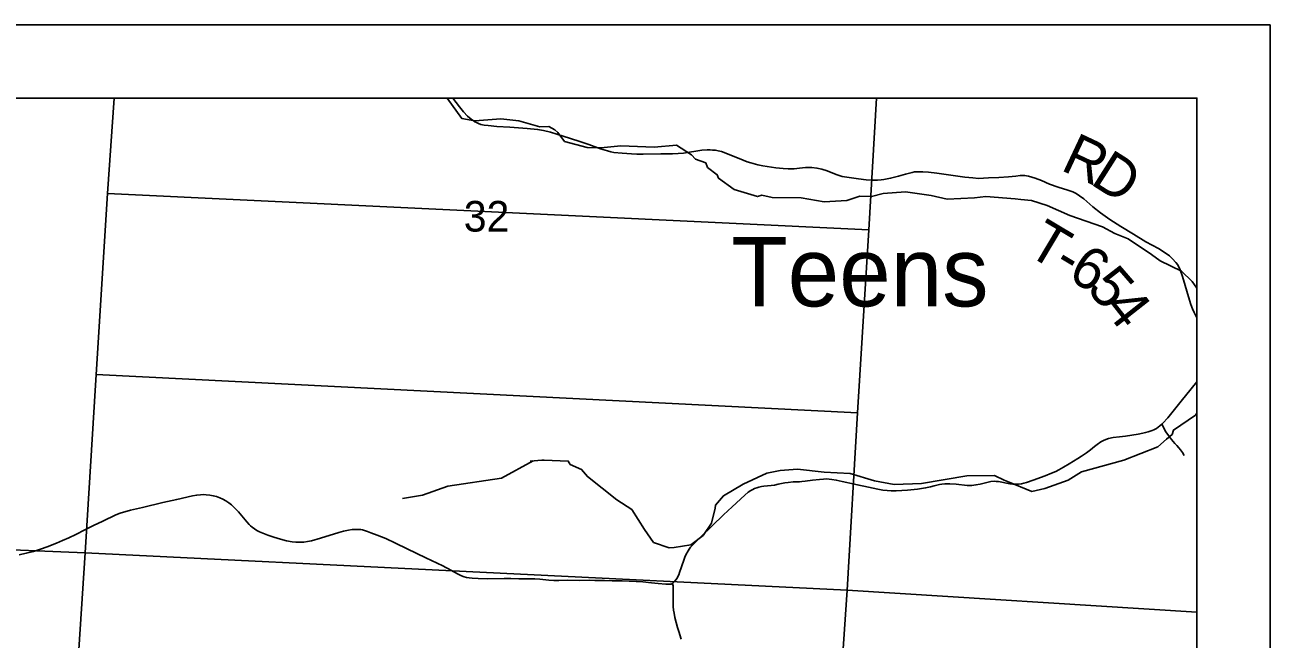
# Model space of a CAD drawing. Extents: x 0 to 34, y 0 to 22.
# Drawn here: x 7.297 to 9, y 20.161 to 21 of the extents above; entities that cross this region are included whole.
import ezdxf

# ---------------------------------------------------------------- set-up
doc = ezdxf.new("R2010")
doc.units = 0
for name, color, linetype in [('Default', 7, 'Continuous'), ('GM_X_County_Road', 7, 'Continuous'), ('GM_X_Minor_River', 7, 'Continuous'), ('GM_X_Minor_River_Text', 7, 'Continuous'), ('GM_X_Section', 7, 'Continuous'), ('GM_X_Section_Text', 7, 'Continuous'), ('GM_X_Township_Road', 7, 'Continuous'), ('GM_X_Township_Road_Text', 7, 'Continuous'), ('SH_Cut_Line', 7, 'Continuous'), ('SH_Data', 7, 'Continuous')]:
    doc.layers.add(name, color=color, linetype=linetype)

msp = doc.modelspace()

# ---------------------------------------------------------------- linework, layer by layer
at = {"layer": 'Default'}
for points in [[(7.4193, 20.9), (6.3675, 20.9), (6.3282, 20.3221), (7.3795, 20.2788), (7.3949, 20.5225), (7.4104, 20.7697)], [(8.4618, 20.9), (7.4193, 20.9), (7.4104, 20.7697), (8.4511, 20.7202)], [(8.9, 20.1978), (8.9, 20.9), (8.4618, 20.9), (8.4511, 20.7202), (8.4356, 20.4701), (8.4216, 20.2279)], [(8.9, 19.9376), (8.9, 20.1978), (8.4216, 20.2279), (8.4033, 19.9608)]]:
    msp.add_lwpolyline(points, close=True, dxfattribs=at)
msp.add_lwpolyline([(7.1944, 19.2649), (8.4872, 19.2008), (8.8731, 19.181), (8.9, 19.1797), (8.9, 20.9), (6.3694, 20.9)], dxfattribs=at)
at = {"layer": 'GM_X_County_Road'}
for points in [[(7.2893, 20.2761), (7.299, 20.2783), (7.3088, 20.2808), (7.3184, 20.2837), (7.3277, 20.287), (7.3404, 20.2921), (7.3486, 20.2955), (7.3575, 20.2995), (7.3668, 20.304), (7.379, 20.3103), (7.391, 20.3163), (7.4037, 20.3223), (7.4217, 20.3305), (7.4273, 20.3328), (7.4323, 20.3345), (7.437, 20.3359), (7.4416, 20.3371), (7.458, 20.3408), (7.4859, 20.3475), (7.5048, 20.3519), (7.5265, 20.3566), (7.5322, 20.3576), (7.5375, 20.3582), (7.5413, 20.3583), (7.5452, 20.3582), (7.55, 20.3576), (7.5547, 20.3569), (7.5593, 20.3557), (7.5637, 20.3541), (7.5678, 20.3522), (7.572, 20.3498), (7.576, 20.3471), (7.5798, 20.3442), (7.5831, 20.3414), (7.5859, 20.3385), (7.5893, 20.3348), (7.5961, 20.3265), (7.6005, 20.3213), (7.6039, 20.3176), (7.6057, 20.3158), (7.6078, 20.314), (7.6112, 20.3114), (7.6146, 20.3094), (7.6181, 20.3075), (7.6225, 20.3056), (7.6296, 20.3029), (7.6377, 20.3001), (7.6466, 20.2975), (7.655, 20.2954), (7.6629, 20.294), (7.6678, 20.2934), (7.6711, 20.2932), (7.6745, 20.2932), (7.6788, 20.2935), (7.6836, 20.2942), (7.689, 20.2954), (7.7015, 20.299), (7.7264, 20.3065), (7.733, 20.3083), (7.7399, 20.3098), (7.7449, 20.3105), (7.7498, 20.3108), (7.7523, 20.3108), (7.7545, 20.3108), (7.7568, 20.3105), (7.759, 20.3101), (7.7617, 20.3094), (7.7657, 20.3081), (7.7704, 20.3063), (7.779, 20.3031), (7.7907, 20.2982), (7.8041, 20.292), (7.8198, 20.2845), (7.8454, 20.2722), (7.8688, 20.2609), (7.8728, 20.2589), (7.8766, 20.257), (7.8798, 20.2552), (7.8886, 20.2501), (7.8915, 20.2486), (7.8945, 20.2473), (7.8978, 20.2461), (7.9011, 20.2452), (7.9048, 20.2445), (7.9088, 20.2441), (7.9172, 20.2437), (7.9298, 20.2433), (7.9524, 20.2439), (7.9619, 20.2439), (7.9729, 20.2433), (7.9883, 20.2433), (7.9945, 20.2432), (8.0012, 20.2428), (8.0139, 20.2413), (8.0206, 20.2409), (8.0274, 20.2411), (8.0398, 20.2414), (8.0562, 20.2412), (8.0692, 20.2413), (8.0767, 20.2412), (8.09, 20.2408), (8.1002, 20.2407), (8.1138, 20.2406), (8.1234, 20.2403), (8.1331, 20.2398), (8.1424, 20.2391), (8.1541, 20.238), (8.1634, 20.2368), (8.1737, 20.2358), (8.1778, 20.2358), (8.181, 20.2361), (8.1828, 20.237), (8.1852, 20.2393), (8.1874, 20.2418), (8.189, 20.2441), (8.1903, 20.2463), (8.1913, 20.2488), (8.1926, 20.2521), (8.1983, 20.2687), (8.1998, 20.2729), (8.2012, 20.2759), (8.2041, 20.2815), (8.2057, 20.284), (8.2076, 20.2865), (8.212, 20.2913), (8.2215, 20.3007), (8.2527, 20.3306), (8.2644, 20.3416), (8.2815, 20.3575), (8.2863, 20.3615), (8.29, 20.3639), (8.2927, 20.3654), (8.2951, 20.3665), (8.298, 20.3676), (8.3008, 20.3685), (8.3044, 20.3693), (8.3075, 20.3697), (8.3176, 20.3707), (8.3223, 20.3713), (8.3274, 20.3724), (8.3365, 20.3743), (8.3412, 20.375), (8.3477, 20.3756), (8.3563, 20.3759), (8.3598, 20.3762), (8.3642, 20.3766), (8.3742, 20.3779), (8.3836, 20.3791), (8.3891, 20.3796), (8.394, 20.3797), (8.3972, 20.3796), (8.4006, 20.3792), (8.4068, 20.3782), (8.4146, 20.3763), (8.4318, 20.3725), (8.4377, 20.3713), (8.4444, 20.3699), (8.4509, 20.3684), (8.4636, 20.3658), (8.4704, 20.3645), (8.4762, 20.3638), (8.4817, 20.3634), (8.4885, 20.3634), (8.504, 20.3645), (8.5179, 20.3658), (8.5288, 20.3676), (8.5354, 20.3691), (8.5406, 20.3705), (8.548, 20.3722), (8.5512, 20.3726), (8.5552, 20.373), (8.5583, 20.373), (8.5621, 20.3729), (8.5706, 20.3724), (8.5856, 20.371), (8.5892, 20.3709), (8.5921, 20.371), (8.5977, 20.3715), (8.6035, 20.3728), (8.6127, 20.3751), (8.6179, 20.3762), (8.6226, 20.3765), (8.6256, 20.3764), (8.6287, 20.3761), (8.6443, 20.3732), (8.648, 20.3727), (8.6518, 20.3725), (8.656, 20.3728), (8.66, 20.3732), (8.6633, 20.3738), (8.667, 20.3748), (8.676, 20.3779), (8.6923, 20.384), (8.7013, 20.3877), (8.7069, 20.39), (8.7111, 20.3922), (8.7176, 20.3959), (8.7251, 20.4003), (8.7371, 20.4075), (8.7423, 20.4107), (8.7488, 20.4153), (8.7543, 20.4195), (8.7598, 20.424), (8.7636, 20.427), (8.7687, 20.4304), (8.7731, 20.4328), (8.7789, 20.435), (8.7854, 20.4363), (8.7939, 20.4374), (8.8021, 20.4384), (8.8197, 20.4411), (8.8258, 20.4423), (8.8297, 20.4431), (8.8331, 20.444), (8.836, 20.4449), (8.8388, 20.446), (8.8412, 20.447), (8.8445, 20.4487), (8.847, 20.4504), (8.8492, 20.4521), (8.8521, 20.4546), (8.8532, 20.4558), (8.86, 20.4633), (8.8782, 20.4859), (8.8922, 20.5029), (8.9, 20.5124)], [(8.1948, 20.1609), (8.1913, 20.1715), (8.1896, 20.1768), (8.1877, 20.1838), (8.1861, 20.1903), (8.1849, 20.1964), (8.1843, 20.2005), (8.1839, 20.2053), (8.1837, 20.2099), (8.1836, 20.2148), (8.1837, 20.2255), (8.1838, 20.2337), (8.1828, 20.237)]]:
    msp.add_lwpolyline(points, dxfattribs=at)
at = {"layer": 'GM_X_Minor_River'}
for points in [[(8.9, 20.6406), (8.8933, 20.6494), (8.8789, 20.6635), (8.8498, 20.6775), (8.838, 20.6862), (8.8059, 20.7078), (8.7877, 20.715), (8.7707, 20.724), (8.7261, 20.7395), (8.6951, 20.7535), (8.6739, 20.7603), (8.6592, 20.7614), (8.6516, 20.7622), (8.6115, 20.7655), (8.596, 20.7636), (8.5586, 20.7619), (8.5363, 20.7668), (8.5015, 20.7721), (8.4709, 20.7697), (8.455, 20.7655), (8.4391, 20.7659), (8.421, 20.7601), (8.3904, 20.7581), (8.3586, 20.7638), (8.3189, 20.7644), (8.3049, 20.7674), (8.2989, 20.7655), (8.2671, 20.7753), (8.2459, 20.7905), (8.244, 20.7954), (8.2308, 20.8053), (8.2282, 20.8114), (8.2142, 20.8167), (8.2089, 20.8227), (8.1884, 20.8356), (8.1578, 20.8329), (8.1121, 20.8347), (8.0849, 20.8319), (8.066, 20.8327), (8.0353, 20.8406), (8.0259, 20.8531), (8.0217, 20.8569), (8.0138, 20.8614), (8.0013, 20.861), (7.9725, 20.8689), (7.948, 20.8719), (7.9124, 20.8692), (7.8947, 20.8722), (7.8749, 20.9)], [(8.9, 20.4696), (8.898, 20.467), (8.8678, 20.4464), (8.8659, 20.4407), (8.8583, 20.4342), (8.8466, 20.4235), (8.8002, 20.4052), (8.7423, 20.3895), (8.7238, 20.378), (8.6921, 20.3665), (8.6743, 20.3627), (8.641, 20.3763), (8.6365, 20.3782), (8.6233, 20.3846), (8.5851, 20.3838), (8.5235, 20.3737), (8.4861, 20.3721), (8.4592, 20.377), (8.4259, 20.3872), (8.3904, 20.389), (8.3537, 20.3931), (8.3299, 20.3911), (8.3118, 20.3877), (8.2793, 20.3728), (8.2525, 20.3568), (8.2415, 20.3438), (8.2411, 20.34), (8.2362, 20.3195), (8.2249, 20.3027), (8.2079, 20.2897), (8.1849, 20.2863), (8.1781, 20.2855), (8.1569, 20.293), (8.1444, 20.3109), (8.127, 20.3378), (8.1065, 20.3511), (8.0664, 20.3829), (8.0585, 20.3928), (8.043, 20.3996), (8.0403, 20.4042), (8.0074, 20.4056), (8.004, 20.4056), (7.9882, 20.404)], [(7.9922, 20.4044), (7.9492, 20.3806), (7.8755, 20.3697), (7.8408, 20.3575), (7.8138, 20.3531)]]:
    msp.add_lwpolyline(points, dxfattribs=at)
at = {"layer": 'GM_X_Section'}
for points in [[(7.4104, 20.7697), (8.4511, 20.7202), (8.4356, 20.4701), (7.3949, 20.5225)], [(8.4356, 20.4701), (8.4216, 20.2279), (7.3795, 20.2788), (7.3949, 20.5225)], [(6.3282, 20.3221), (7.3795, 20.2788), (7.3627, 20.0215), (7.3466, 19.7773), (7.3307, 19.5247), (7.3152, 19.2658), (6.2595, 19.3129)], [(8.4216, 20.2279), (8.4033, 19.9608), (7.3627, 20.0215), (7.3795, 20.2788)]]:
    msp.add_lwpolyline(points, close=True, dxfattribs=at)
at = {"layer": 'GM_X_Township_Road'}
for points in [[(7.8825, 20.9), (7.8915, 20.8883), (7.897, 20.8814), (7.9027, 20.8755), (7.9077, 20.8712), (7.9101, 20.8694), (7.9126, 20.8678), (7.9149, 20.8666), (7.9174, 20.8653), (7.9209, 20.8641), (7.9251, 20.8631), (7.9309, 20.8624), (7.9428, 20.8614), (7.9605, 20.8603), (7.9841, 20.8587), (7.9984, 20.8573), (8.0063, 20.8559), (8.016, 20.8536), (8.0334, 20.8479), (8.0545, 20.841), (8.0682, 20.8366), (8.0844, 20.8309), (8.0939, 20.8278), (8.0987, 20.8265), (8.1028, 20.8259), (8.1139, 20.8247), (8.1266, 20.8237), (8.134, 20.8234), (8.1429, 20.8234), (8.1668, 20.8237), (8.1827, 20.824), (8.1907, 20.8244), (8.1977, 20.8248), (8.223, 20.8287), (8.2301, 20.8293), (8.2341, 20.8293), (8.2376, 20.8291), (8.2415, 20.8287), (8.2452, 20.8282), (8.2498, 20.8269), (8.2605, 20.8231), (8.2796, 20.8151), (8.2849, 20.8131), (8.2899, 20.8116), (8.2995, 20.809), (8.3062, 20.8076), (8.3123, 20.8066), (8.324, 20.805), (8.3341, 20.8039), (8.3411, 20.8034), (8.3453, 20.8034), (8.3491, 20.8036), (8.3565, 20.8044), (8.3646, 20.8051), (8.3693, 20.8053), (8.3733, 20.8051), (8.3802, 20.8045), (8.3869, 20.803), (8.3941, 20.8008), (8.4064, 20.7957), (8.412, 20.7939), (8.4148, 20.7931), (8.4179, 20.7925), (8.4373, 20.7899), (8.4477, 20.7884), (8.4563, 20.7879), (8.463, 20.7879), (8.4682, 20.7883), (8.472, 20.7889), (8.4811, 20.7906), (8.4919, 20.7935), (8.5014, 20.7962), (8.5069, 20.7977), (8.5104, 20.7985), (8.5138, 20.7991), (8.519, 20.7995), (8.5253, 20.7994), (8.5331, 20.7987), (8.5442, 20.7975), (8.5824, 20.7921), (8.5934, 20.7909), (8.6012, 20.7904), (8.6151, 20.7909), (8.6291, 20.7915), (8.6423, 20.7923), (8.6523, 20.7936), (8.6582, 20.7943), (8.6614, 20.7945), (8.6643, 20.7943), (8.6695, 20.7934), (8.6743, 20.7922), (8.6788, 20.7907), (8.6875, 20.7873), (8.6984, 20.7826), (8.7102, 20.7782), (8.7236, 20.7742), (8.7301, 20.7719), (8.7346, 20.7697), (8.7394, 20.7667), (8.7453, 20.7622), (8.7574, 20.7516), (8.7681, 20.7435), (8.7808, 20.734), (8.7957, 20.7248), (8.8131, 20.7141), (8.8302, 20.7039), (8.8475, 20.6944), (8.8564, 20.6888), (8.8625, 20.6844), (8.8667, 20.6806), (8.8712, 20.6754), (8.8737, 20.6722), (8.8771, 20.6654), (8.8803, 20.6562), (8.8899, 20.6241), (8.8918, 20.6181), (8.8939, 20.612), (8.896, 20.6072), (8.8985, 20.6024), (8.9, 20.5998)], [(8.8826, 20.4118), (8.8801, 20.4158), (8.8775, 20.4193), (8.8752, 20.4221), (8.8724, 20.4253), (8.8696, 20.4284), (8.8651, 20.4336), (8.8609, 20.439), (8.8574, 20.4441), (8.8557, 20.4473), (8.8528, 20.453), (8.8521, 20.4546)]]:
    msp.add_lwpolyline(points, dxfattribs=at)
at = {"layer": 'SH_Cut_Line'}
msp.add_lwpolyline([(8.9, 14.1), (8.9, 20.9), (2.1, 20.9), (2.1, 14.1)], dxfattribs=at)
at = {"layer": 'SH_Data'}
for p, q in [((2, 21), (9, 21)), ((9, 21), (9, 14)), ((2.1, 20.9), (8.9, 20.9)), ((8.9, 20.9), (8.9, 14.1))]:
    msp.add_line(p, q, dxfattribs=at)

# ---------------------------------------------------------------- texts
at = {"layer": 'GM_X_Minor_River_Text'}
msp.add_text('Teens', height=0.0947, rotation=359.9977, dxfattribs=at).set_placement((8.263, 20.6155))
at = {"layer": 'GM_X_Section_Text'}
msp.add_text('32', height=0.04186, rotation=0, dxfattribs=at).set_placement((7.8974, 20.7177))
at = {"layer": 'GM_X_Township_Road_Text'}
for s, rotation, p in [('R', 334.7983, (8.712, 20.8025)), ('D', 327.6008, (8.7526, 20.7835)), ('T', 329.1935, (8.6648, 20.6879)), ('6', 329.1697, (8.7214, 20.6542)), ('-', 329.1895, (8.7013, 20.6662)), ('5', 310.971, (8.7478, 20.6393)), ('4', 308.1819, (8.7703, 20.6135))]:
    msp.add_text(s, height=0.0568, rotation=rotation, dxfattribs=at).set_placement(p)

doc.saveas('drawing.dxf')
